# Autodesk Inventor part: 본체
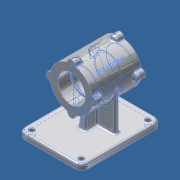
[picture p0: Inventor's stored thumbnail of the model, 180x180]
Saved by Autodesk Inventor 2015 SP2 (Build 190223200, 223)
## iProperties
Created: 2015-12
Part Number: 본체
Material: 알루미늄 6061
Document SubType Name: Modeling
Designer: AMC
Density: 2.7 g/cm^3
Appearance: 알루미늄 - 평지
Mass: 1160.29 g
Surface Area: 814.904 cm^2
Volume: 429.736 cm^3
Author: AMC
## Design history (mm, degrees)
sketch "스케치1"
  geometry: L1 (-55, -70)-(55, -70); L2 (55, -70)-(55, -80); L3 (55, -80)-(-55, -80); L4 (-55, -80)-(-55, -70); C1 r 37 at (0, 0); 2 further points
  constraints: 8 end point, 2 parallel, 1 centre point, 1 coincident, 1 horizontal, 1 midpoint, 1 perpendicular, 1 vertical alignment
  dimensions: "d0" = 74 diameter of C1; "d1" = 110 distance of L1.start L1.end; "d2" = 10 distance of L3.end L1.start; "d3" = 80 distance from line of L3 point (0, 0)
extrude "돌출1" new body sketch "스케치1" stored distance "d4" = 85; taper "d5" = 0 deg
extrude "돌출2" join sketch "스케치1" distance "d6" = 80; taper "d8" = 0 deg; dims "d7" = 60, "d9" = 0
node "작업 평면1"
sketch "스케치2"
  geometry: L1 (55, -70)-(-55, -70) reference; L2 (37, 0)-(37, -70); L3 (-37, 0)-(-37, -70); L4 (-37, -70)-(37, -70); A1 r 37 centre (0, 0) between (37, 0) and (-37, 0) reference; A2 r 37 centre (0, 0) between (-37, 0) and (37, 0); 1 further point
  constraints: 6 end point, 4 point on circle, 2 perpendicular, 2 point on line, 2 tangent, 1 centre point, 1 coincident, 1 horizontal
extrude "돌출3" join sketch "스케치2" stored distance "d11" = 8; taper "d12" = 0 deg
node "작업 평면2"
sketch "스케치3"
  geometry: L1 (-70, 80)-(-70, -60) reference; L2 (-70, 4)-(0, 4) reference; L3 (-37, -42.5)-(-37, 42.5) reference; L4 (-37, 20.948)-(-70, 25); L5 (0, 0)-(-70, 0)
  constraints: 4 end point, 3 point on line, 1 perpendicular
  dimensions: "d14" = 25 distance of L4.end L5.end; "d15" = 97 deg angle of L1 L4
feature "리브1" sketch "스케치3" dims "d16" = 1, "d17" = 12, "d18" = 0, "d19" = 0, "d20" = 1, "d21" = 1
fillet "모깎기1" dims "d22" = 12
sketch "스케치4"
  geometry: L1 (-12, 128)-(-12, 12) reference; L2 (86, 0)-(0, 0) reference; L3 (98, 12)-(98, 128) reference; L4 (0, 140)-(86, 140) reference; L5 (37, 55)-(37, 76) reference; L6 (37, 76)-(6, 76) reference; L7 (6, 76)-(6, 84) reference; L8 (6, 84)-(37, 84) reference; L9 (37, 84)-(37, 105) reference; L10 (37, 105)-(49, 105) reference; L11 (49, 105)-(49, 84) reference; L12 (49, 84)-(80, 84) reference; L13 (80, 84)-(80, 76) reference; L14 (80, 76)-(49, 76) reference; L15 (49, 76)-(49, 55) reference; L16 (49, 55)-(37, 55) reference; A1 r 12 centre (0, 12) between (-12, 12) and (0, 0) reference; A2 r 12 centre (0, 128) between (0, 140) and (-12, 128) reference; A3 r 12 centre (0, 12) between (-12, 12) and (0, 0) reference; A4 r 12 centre (86, 12) between (86, 0) and (98, 12) reference; A5 r 12 centre (86, 128) between (98, 128) and (86, 140) reference; 5 further points
  constraints: 4 coincident
hole "구멍1" sketch "스케치4" at (0, 12), (86, 12), (0, 128), (86, 128) diameter "d23" = 8; stored, may be unused: countersink angle "d27" = 90 deg, drill point angle "d29" = 118 deg; dims "d24" = 6, "d25" = 4, "d26" = 2, "d28" = 10
hole "구멍2" diameter "d32" = 42; stored, may be unused: countersink angle "d36" = 90 deg, drill point angle "d38" = 118 deg; dims "d30" = 10, "d31" = 10, "d33" = 6, "d34" = 47, "d35" = 22, "d37" = 10
hole "구멍3" diameter "d41" = 42; stored, may be unused: countersink angle "d45" = 90 deg, drill point angle "d47" = 118 deg; dims "d39" = 10, "d40" = 10, "d42" = 6, "d43" = 47, "d44" = 22, "d46" = 10
fillet "모깎기2" dims "d53" = 3
fillet "모깎기3" dims "d54" = 3
fillet "모깎기4" dims "d55" = 3
chamfer "모따기1" distance "d56" = 1; stored, may be unused: second distance "d57" = 2, angle "d58" = 45 deg
node "작업 평면3"
sketch "스케치6"
  geometry: L1 (0, 0)-(26.163, 26.163); L2 (0, 0)-(37, 0); 1 further point
  constraints: 4 end point, 1 equal length, 1 horizontal, 2 other
  dimensions: "d60" = 45 deg angle of L2 L1
node "작업 평면4"
sketch "스케치7"
  geometry: 2 further points
  constraints: 1 coincident, 1 other
feature "엠보싱1" sketch "스케치7" dims "d61" = 0.5, "d62" = 0
node "작업 평면6"
sketch "스케치11"
  geometry: L1 (0, 0)-(0, 37); A1 r 37 centre (0, 0) between (6.969, 36.338) and (-6.969, 36.338); A2 r 7 centre (0, 37) between (6.969, 36.338) and (-6.969, 36.338); 2 further points
  constraints: 4 point on circle, 3 coincident, 2 centre point, 2 end point, 1 vertical, 1 vertical alignment, 2 other
  dimensions: "d68" = 14 diameter of A2
extrude "돌출4" join sketch "스케치11" distance "d69" = 12.452; taper "d70" = 0 deg
node "작업 평면7"
sketch "스케치12"
  geometry: L1 (44, 42.5)-(44, 30.048) reference; L2 (36.338, 30.048)-(44, 30.048) reference; L3 (37, -42.5)-(37, 30.048) reference; L4 (44, 30.048)-(37, 27.5); L5 (44, 30.048)-(37, 30.048); L6 (37, 27.5)-(37, 30.048); L7 (37, 27.5)-(37, 30.048); 1 further point
  constraints: 8 end point, 3 collinear, 1 point on line
  dimensions: "d75" = 110 deg angle of L3 L4
revolve "회전1" sketch "스케치12" stored, may be unused: angle "d76" = 90 deg
fillet "모깎기5" dims "d77" = 3
hole "구멍4" diameter "d80" = 3.242; stored, may be unused: countersink angle "d84" = 90 deg, drill point angle "d86" = 118 deg; dims "d78" = 10, "d79" = 10, "d81" = 9, "d82" = 2, "d83" = 22, "d85" = 11
fillet "모깎기6" dims "d90" = 0.3
node "솔리드1"
mirror "대칭1"
pattern_circular "원형 패턴1" dims "d88" = 360 deg
mirror "대칭2"
node "투영된 루프1"
other parameters: "d10" = 0, "d13" = 0, "d59" = 0, "d67" = 0, "d71" = 0
